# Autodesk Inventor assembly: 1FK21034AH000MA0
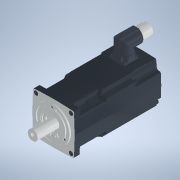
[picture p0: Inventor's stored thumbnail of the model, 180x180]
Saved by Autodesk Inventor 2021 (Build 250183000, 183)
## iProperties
Category: PARTsolutions
Created: 2026-06
Part Number: 1FK21034AH000MA0
Catalog Web Link: www.3dfindit.com
Description: 1FK21034AH000MA0-Servo synchronous motor
Document SubType Name: Assembly
Designer: psAdmin
Mass: 247.009 g
Surface Area: 862.933 cm^2
Volume: 247.009 cm^3
Density: 1 g/cm^3
Title: 1FK21034AH000MA0
Author: Cadenas PARTsolutions
Comments: Servo synchronous motor
PSOL_IDENT_0: {$CADENAS_DATA/23d-libs/siemens_ag/_cat_/ec/b7/1fk21034ah000ma0.prj},193 {STYP=ASS},{VTYP=3D},{NB=1F
PSOL_IDENT_1: K21034AH000MA0},{LINA=1FK21034AH000MA0},{NN=1FK21034AH000MA0},{DATE=19.08.2025 14:01:05},{GEOMDATE=3
PSOL_IDENT_2: 0.07.2025 02:01:02},{VERSION=},{LINEID=10},{WBVAR=},{WBNUMERIC=}  {NB=1FK21034AH000MA0},{LINA=1FK210
PSOL_IDENT_3: 34AH000MA0},{KT=DUMMY},{PREVIEW=../../../_pool_/7c/50/p_d211_xx_00932j.png},{DESCSHORT=SIMOTICS S-1F
PSOL_IDENT_4: K2 HD, SINAMICS S210 3AC 400V-480V, 1.01 Nm, 4500 rpm},{DESCLONG=SIMOTICS S-1FK2 HD servo motor M0=1
PSOL_IDENT_5: .27 Nm; PN = 0.48 kW at nN=4500 rpm (380-480 V); PN = 0.3 kW at nN=2500 rpm (200-240 V); degree of p
PSOL_IDENT_6: rotection IP64; cylindrical shaft D14 x 30 mm; absolute encoder 22-bit + 12-bit multiturn (encoder A
PSOL_IDENT_7: M22DQC); with OCC interface; plug size M17, rotatable; SIMOTICS S-1FK2 servomotorfor a wide range of
PSOL_IDENT_8: uses in industrial environments. SIMOTICS S‑1FK2 servomotors are compact synchronous motors with a
PSOL_IDENT_9: high dynamic performance that set themselves apart as a result of their high power density, degree o
PSOL_IDENT_10: f protection and overload capability. The motors are available in two variants: as High Dynamic vari
PSOL_IDENT_11: ant (highest dynamic performance as a result of the low intrinsic moment of inertia for applications
PSOL_IDENT_12: demanding a high dynamic performance with low moved masses) - and as Compact variant (precise and s
PSOL_IDENT_13: table closed-loop control for medium up to large moved masses as a result of a medium intrinsic mome
PSOL_IDENT_14: nt of inertia). SIMOTICSS‑1FK2 servomotors fully exploit their strengths in a system with the SINAMI
PSOL_IDENT_15: CSS210 frequency converter and simple connection using the one cable connection (OCC). Advantages in
PSOL_IDENT_16: clude the short control and positioning times, fast and precise correction of disturbing quantities
PSOL_IDENT_17: as well as stable control with a high dynamic performance. The servo motors can be configured to add
PSOL_IDENT_18: ress a wide range of requirements. For example with and without holding brake, IP64 or IP65 degree o
PSOL_IDENT_19: f protection, singleturn or multiturn absolute encoders - to name just a few. Further, the servomoto
PSOL_IDENT_20: rs are available in different shaft heights extending from 20 to 100. A shaft sealing ring is availa
PSOL_IDENT_21: ble to achieve an IP65 degree of protection and for subsequent mounting at the motor or as spare par
PSOL_IDENT_22: t. SIMOTICS - the optimum motor for each and every motion control application.},{INTNO=4034106444822
PSOL_IDENT_23: },{SUPPLIERALTNO=1FK2103-4AH00-0MA0},{MANUID=1FK21034AH000MA0},{MANUNAME=Siemens},{MANUTYPEDESC=SYNC
PSOL_IDENT_24: HRONOUS MOTOR 1FK2 HD 1,27 NM},{AAU732=SIMOTICS},{AAO057=S-1FK2},{AAU734=SIMOTICS S-1FK2 HD servo mo
PSOL_IDENT_25: tor M0=1.27 Nm; PN = 0.48 kW at nN=4500 rpm (380-480 V); PN = 0.3 kW at nN=2500 rpm (200-240 V); deg
PSOL_IDENT_26: ree of protection IP64; cylindrical shaft D14 x 30 mm; absolute encoder 22-bit + 12-bit multiturn (e
PSOL_IDENT_27: ncoder AM22DQC); with OCC interface; plug size M17, rotatable;},{AAW338=SYNCHRONOUS MOTOR 1FK2 HD 1,
PSOL_IDENT_28: 27 NM},{AAO742=SIMOTICS},{AAO663=4034106444822},{NOCUPEROU=1},{PRICEQUANTITY=1},{QUANTITYMIN=1},{QUA
PSOL_IDENT_29: NTITYINT=1},{CTN=85015100},{COO=RO},{AAO676=1FK2103-4AH00-0MA0},{AAO677=Siemens AG},{ORDERUNIT=C62},
PSOL_IDENT_30: {CONTENTUNIT=C62}
NB: 1FK21034AH000MA0
NN: 1FK21034AH000MA0
NT: Servo synchronous motor
NBSYN: $MANUID.
LINA: 1FK21034AH000MA0
CATALOG: SIEMENS
PREVIEW: ../../../_pool_/7c/50/p_d211_xx_00932j.png
DESCSHORT: SIMOTICS S-1FK2 HD, SINAMICS S210 3AC 400V-480V, 1.01 Nm, 4500 rpm
DESCLONG: SIMOTICS S-1FK2 HD servo motor M0=1.27 Nm; PN = 0.48 kW at nN=4500 rpm (380-480 V); PN = 0.3 kW at nN=2500 rpm (200-240 V); degree of protection IP64; cylindric
INTNO: 4034106444822
SUPPLIERALTNO: 1FK2103-4AH00-0MA0
MANUID: 1FK21034AH000MA0
MANUNAME: Siemens
MANUTYPEDESC: SYNCHRONOUS MOTOR 1FK2 HD 1,27 NM
AAU732: SIMOTICS
AAO057: S-1FK2
AAU734: SIMOTICS S-1FK2 HD servo motor M0=1.27 Nm; PN = 0.48 kW at nN=4500 rpm (380-480 V); PN = 0.3 kW at nN=2500 rpm (200-240 V); degree of protection IP64; cylindric
AAW338: SYNCHRONOUS MOTOR 1FK2 HD 1,27 NM
AAO742: SIMOTICS
AAO663: 4034106444822.0
NOCUPEROU: 1
PRICEQUANTITY: 1
QUANTITYMIN: 1
QUANTITYINT: 1
CTN: 85015100
COO: RO
ARTICLENO: 1FK21034AH000MA0
BOMINFO: 1FK21034AH000MA0
CREATOR: CADENAS GmbH
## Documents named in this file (25)
- e:\temp\worker_COMMON_12\temp\tmp_2820_6_B6ks4\format_0\1FK21034AH000MA0.iam
- e:\temp\worker_COMMON_12\temp\tmp_2820_6_B6ks4\format_0\1FK21034AH000MA0_PART1.ipt
- e:\temp\worker_COMMON_12\temp\tmp_2820_6_B6ks4\format_0\1FK21034AH000MA0_PART2.ipt
- e:\temp\worker_COMMON_12\temp\tmp_2820_6_B6ks4\format_0\1FK21034AH000MA0_PART3.ipt
- e:\temp\worker_COMMON_12\temp\tmp_2820_6_B6ks4\format_0\1FK21034AH000MA0_PART4.ipt
- e:\temp\worker_COMMON_12\temp\tmp_2820_6_B6ks4\format_0\1FK21034AH000MA0_PART5.ipt
- e:\temp\worker_COMMON_12\temp\tmp_2820_6_B6ks4\format_0\1FK21034AH000MA0_PART6.ipt
- e:\temp\worker_COMMON_12\temp\tmp_2820_6_B6ks4\format_0\1FK21034AH000MA0_PART7.ipt
- e:\temp\worker_COMMON_12\temp\tmp_2820_6_B6ks4\format_0\1FK21034AH000MA0_PART8.ipt
- e:\temp\worker_COMMON_12\temp\tmp_2820_6_B6ks4\format_0\1FK21034AH000MA0_PART9.ipt
- e:\temp\worker_COMMON_12\temp\tmp_2820_6_B6ks4\format_0\1FK21034AH000MA0_PART10.ipt
- e:\temp\worker_COMMON_12\temp\tmp_2820_6_B6ks4\format_0\1FK21034AH000MA0_PART11.ipt
- e:\temp\worker_COMMON_12\temp\tmp_2820_6_B6ks4\format_0\1FK21034AH000MA0_PART12.ipt
- e:\temp\worker_COMMON_12\temp\tmp_2820_6_B6ks4\format_0\1FK21034AH000MA0_PART13.ipt
- e:\temp\worker_COMMON_12\temp\tmp_2820_6_B6ks4\format_0\1FK21034AH000MA0_PART14.ipt
- e:\temp\worker_COMMON_12\temp\tmp_2820_6_B6ks4\format_0\1FK21034AH000MA0_PART15.ipt
- e:\temp\worker_COMMON_12\temp\tmp_2820_6_B6ks4\format_0\1FK21034AH000MA0_PART16.ipt
- e:\temp\worker_COMMON_12\temp\tmp_2820_6_B6ks4\format_0\1FK21034AH000MA0_PART17.ipt
- e:\temp\worker_COMMON_12\temp\tmp_2820_6_B6ks4\format_0\1FK21034AH000MA0_PART18.ipt
- e:\temp\worker_COMMON_12\temp\tmp_2820_6_B6ks4\format_0\1FK21034AH000MA0_PART19.ipt
- e:\temp\worker_COMMON_12\temp\tmp_2820_6_B6ks4\format_0\1FK21034AH000MA0_PART20.ipt
- e:\temp\worker_COMMON_12\temp\tmp_2820_6_B6ks4\format_0\1FK21034AH000MA0_PART21.ipt
- e:\temp\worker_COMMON_12\temp\tmp_2820_6_B6ks4\format_0\1FK21034AH000MA0_PART22.ipt
- e:\temp\worker_COMMON_12\temp\tmp_2820_6_B6ks4\format_0\1FK21034AH000MA0_PART23.ipt
- e:\temp\worker_COMMON_12\temp\tmp_2820_6_B6ks4\format_0\1FK21034AH000MA0_PART24.ipt
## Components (24 placed, 24 different names)
1. 1FK21034AH000MA0_PART1:1
2. 1FK21034AH000MA0_PART2:1
3. 1FK21034AH000MA0_PART3:1
4. 1FK21034AH000MA0_PART4:1
5. 1FK21034AH000MA0_PART5:1
6. 1FK21034AH000MA0_PART6:1
7. 1FK21034AH000MA0_PART7:1
8. 1FK21034AH000MA0_PART8:1
9. 1FK21034AH000MA0_PART9:1
10. 1FK21034AH000MA0_PART10:1
11. 1FK21034AH000MA0_PART11:1
12. 1FK21034AH000MA0_PART12:1
13. 1FK21034AH000MA0_PART13:1
14. 1FK21034AH000MA0_PART14:1
15. 1FK21034AH000MA0_PART15:1
16. 1FK21034AH000MA0_PART16:1
17. 1FK21034AH000MA0_PART17:1
18. 1FK21034AH000MA0_PART18:1
19. 1FK21034AH000MA0_PART19:1
20. 1FK21034AH000MA0_PART20:1
21. 1FK21034AH000MA0_PART21:1
22. 1FK21034AH000MA0_PART22:1
23. 1FK21034AH000MA0_PART23:1
24. 1FK21034AH000MA0_PART24:1
